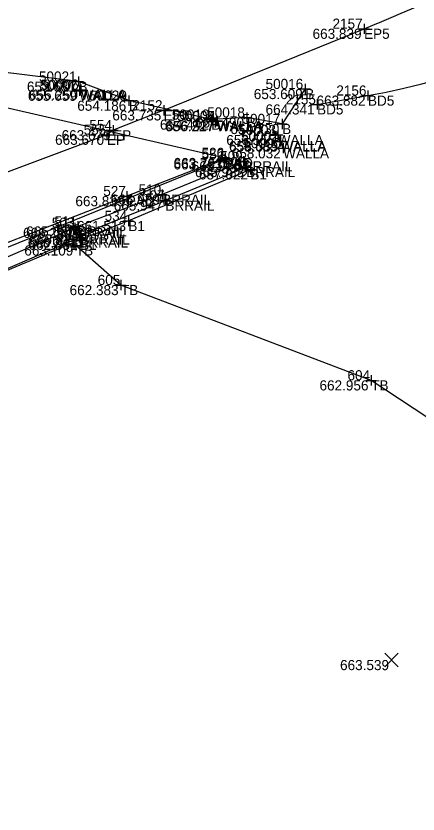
# Model space of a CAD drawing. Extents: x 2197382 to 2204062, y 634117 to 636522.
# Drawn here: x 2202423.3 to 2202463, y 635145.7 to 635224.5 of the extents above; entities that cross this region are included whole.
import ezdxf

# ---------------------------------------------------------------- set-up
doc = ezdxf.new("R2010")
doc.units = 0
for name, color, linetype in [('_CIVIL_CONSTRUCTION', 7, 'Continuous'), ('BR_P_Gen_Approach_Slab', 7, 'Continuous'), ('BR_X_SV_Abut_Text', 7, 'Continuous'), ('BR_X_SV_Deck_Top', 7, 'Continuous'), ('BR_X_SV_Deck_Top_Text', 7, 'Continuous'), ('BR_X_SV_Rail', 7, 'Continuous'), ('GE_P_Alignment_100_Distances', 7, 'Continuous'), ('GE_X_Alignment', 7, 'Continuous'), ('PF_P_Grade_Line', 7, 'Continuous'), ('RW_X_CL_100_Curve_Data', 7, 'Continuous'), ('RW_X_CL_100_Stations', 7, 'Continuous'), ('SH_Border', 7, 'Continuous'), ('SH_Cut_Line', 7, 'Continuous'), ('SH_Data', 7, 'Continuous'), ('SH_Text', 7, 'Continuous')]:
    doc.layers.add(name, color=color, linetype=linetype)

msp = doc.modelspace()

# ---------------------------------------------------------------- linework, layer by layer
at = {"layer": '_CIVIL_CONSTRUCTION'}
for p, q in [((2202457.668, 635223.782), (2202457.668, 635222.782)), ((2202457.168, 635223.282), (2202458.168, 635223.282)), ((2202457.668, 635223.282), (2202457.668, 635223.282)), ((2202429.476, 635218.562), (2202429.476, 635217.562)), ((2202428.976, 635218.062), (2202429.976, 635218.062)), ((2202429.476, 635218.062), (2202429.476, 635218.062)), ((2202429.568, 635217.662), (2202429.568, 635216.662)), ((2202429.705, 635217.763), (2202429.705, 635216.763)), ((2202451.866, 635217.83), (2202451.866, 635216.83)), ((2202429.068, 635217.162), (2202430.068, 635217.162)), ((2202429.205, 635217.263), (2202430.205, 635217.263)), ((2202429.568, 635217.162), (2202429.568, 635217.162)), ((2202429.705, 635217.263), (2202429.705, 635217.263)), ((2202434.466, 635216.679), (2202434.466, 635215.679)), ((2202451.366, 635217.33), (2202452.366, 635217.33)), ((2202451.866, 635217.33), (2202451.866, 635217.33)), ((2202457.551, 635216.681), (2202458.551, 635216.681)), ((2202458.051, 635217.181), (2202458.051, 635216.181)), ((2202458.051, 635216.681), (2202458.051, 635216.681)), ((2202433.966, 635216.179), (2202434.966, 635216.179)), ((2202434.466, 635216.179), (2202434.466, 635216.179)), ((2202453.028, 635216.312), (2202453.028, 635215.312)), ((2202437.39, 635215.225), (2202438.39, 635215.225)), ((2202437.89, 635215.725), (2202437.89, 635214.725)), ((2202437.89, 635215.225), (2202437.89, 635215.225)), ((2202452.528, 635215.812), (2202453.528, 635215.812)), ((2202453.028, 635215.812), (2202453.028, 635215.812)), ((2202442.093, 635214.307), (2202443.093, 635214.307)), ((2202442.593, 635214.807), (2202442.593, 635213.807)), ((2202442.593, 635214.307), (2202442.593, 635214.307)), ((2202443.118, 635214.648), (2202443.118, 635213.648)), ((2202443.18, 635214.673), (2202443.18, 635213.673)), ((2202445.6, 635214.518), (2202446.6, 635214.518)), ((2202446.1, 635215.018), (2202446.1, 635214.018)), ((2202446.1, 635214.518), (2202446.1, 635214.518)), ((2202449.583, 635214.376), (2202449.583, 635213.376)), ((2202432.899, 635213.763), (2202432.899, 635212.763)), ((2202442.618, 635214.148), (2202443.618, 635214.148)), ((2202442.68, 635214.173), (2202443.68, 635214.173)), ((2202443.118, 635214.148), (2202443.118, 635214.148)), ((2202443.18, 635214.173), (2202443.18, 635214.173)), ((2202449.083, 635213.876), (2202450.083, 635213.876)), ((2202449.583, 635213.876), (2202449.583, 635213.876)), ((2202431.787, 635212.815), (2202432.787, 635212.815)), ((2202432.287, 635213.315), (2202432.287, 635212.315)), ((2202432.287, 635212.815), (2202432.287, 635212.815)), ((2202432.399, 635213.263), (2202433.399, 635213.263)), ((2202432.899, 635213.263), (2202432.899, 635213.263)), ((2202448.641, 635212.788), (2202449.641, 635212.788)), ((2202449.141, 635213.288), (2202449.141, 635212.288)), ((2202449.141, 635212.788), (2202449.141, 635212.788)), ((2202448.901, 635212.192), (2202449.901, 635212.192)), ((2202448.93, 635212.14), (2202449.93, 635212.14)), ((2202449.401, 635212.692), (2202449.401, 635211.692)), ((2202449.401, 635212.192), (2202449.401, 635212.192)), ((2202449.43, 635212.64), (2202449.43, 635211.64)), ((2202449.43, 635212.14), (2202449.43, 635212.14)), ((2202449.678, 635211.981), (2202449.678, 635210.981)), ((2202449.178, 635211.481), (2202450.178, 635211.481)), ((2202449.678, 635211.481), (2202449.678, 635211.481)), ((2202443.426, 635210.385), (2202444.426, 635210.385)), ((2202443.45, 635210.52), (2202444.45, 635210.52)), ((2202443.926, 635210.885), (2202443.926, 635209.885)), ((2202443.926, 635210.385), (2202443.926, 635210.385)), ((2202443.95, 635211.02), (2202443.95, 635210.02)), ((2202443.95, 635210.52), (2202443.95, 635210.52)), ((2202445.763, 635210.697), (2202445.763, 635209.697)), ((2202445.263, 635210.197), (2202446.263, 635210.197)), ((2202445.545, 635209.625), (2202446.545, 635209.625)), ((2202445.763, 635210.197), (2202445.763, 635210.197)), ((2202446.045, 635210.125), (2202446.045, 635209.125)), ((2202446.045, 635209.625), (2202446.045, 635209.625)), ((2202446.445, 635209.895), (2202446.445, 635208.895)), ((2202445.945, 635209.395), (2202446.945, 635209.395)), ((2202446.445, 635209.395), (2202446.445, 635209.395)), ((2202434.242, 635207.252), (2202434.242, 635206.252)), ((2202437.75, 635207.408), (2202437.75, 635206.408)), ((2202433.742, 635206.752), (2202434.742, 635206.752)), ((2202434.242, 635206.752), (2202434.242, 635206.752)), ((2202437.25, 635206.908), (2202438.25, 635206.908)), ((2202437.75, 635206.908), (2202437.75, 635206.908)), ((2202438.058, 635206.817), (2202438.058, 635205.817)), ((2202437.558, 635206.317), (2202438.558, 635206.317)), ((2202438.058, 635206.317), (2202438.058, 635206.317)), ((2202429.129, 635204.122), (2202429.129, 635203.122)), ((2202429.41, 635204.264), (2202429.41, 635203.264)), ((2202433.902, 635204.297), (2202434.902, 635204.297)), ((2202434.402, 635204.797), (2202434.402, 635203.797)), ((2202434.402, 635204.297), (2202434.402, 635204.297)), ((2202428.629, 635203.622), (2202429.629, 635203.622)), ((2202428.91, 635203.764), (2202429.91, 635203.764)), ((2202429.129, 635203.622), (2202429.129, 635203.622)), ((2202429.41, 635203.764), (2202429.41, 635203.764)), ((2202429.701, 635203.466), (2202429.701, 635202.466)), ((2202429.059, 635202.673), (2202430.059, 635202.673)), ((2202429.201, 635202.966), (2202430.201, 635202.966)), ((2202429.559, 635203.173), (2202429.559, 635202.173)), ((2202429.559, 635202.673), (2202429.559, 635202.673)), ((2202429.637, 635202.941), (2202429.637, 635201.941)), ((2202429.701, 635202.966), (2202429.701, 635202.966)), ((2202428.719, 635201.88), (2202429.719, 635201.88)), ((2202429.137, 635202.441), (2202430.137, 635202.441)), ((2202429.219, 635202.38), (2202429.219, 635201.38)), ((2202429.219, 635201.88), (2202429.219, 635201.88)), ((2202429.637, 635202.441), (2202429.637, 635202.441)), ((2202433.169, 635197.969), (2202434.169, 635197.969)), ((2202433.669, 635198.469), (2202433.669, 635197.469)), ((2202433.669, 635197.969), (2202433.669, 635197.969)), ((2202457.873, 635188.556), (2202458.873, 635188.556)), ((2202458.373, 635189.056), (2202458.373, 635188.056)), ((2202458.373, 635188.556), (2202458.373, 635188.556))]:
    msp.add_line(p, q, dxfattribs=at)
at = {"layer": 'BR_P_Gen_Approach_Slab'}
msp.add_lwpolyline([(2202443.95, 635210.52), (2202434.242, 635206.752), (2202412.599, 635198.33), (2202410.833, 635202.436), (2202382.459, 635210.634), (2202380.356, 635214.567), (2202398.438, 635220.987)], close=True, dxfattribs=at)
at = {"layer": 'BR_X_SV_Deck_Top'}
msp.add_line((2202453.028, 635215.812), (2202458.051, 635216.681), dxfattribs=at)
msp.add_open_spline([(2202458.051, 635216.681), (2202477.116, 635219.979), (2202511.723, 635243.78), (2202554.955, 635262.299), (2202588.014, 635280.674), (2202608.342, 635292.387), (2202640.833, 635312.137), (2202668.147, 635329.948), (2202698.573, 635351.315), (2202722.135, 635368.649), (2202754.604, 635393.426), (2202777.494, 635412.293), (2202789.607, 635422.635)], degree=3, dxfattribs=at)
at = {"layer": 'BR_X_SV_Rail'}
for points in [[(2202429.701, 635202.966), (2202438.058, 635206.317), (2202446.045, 635209.625), (2202445.763, 635210.197), (2202437.75, 635206.908), (2202429.41, 635203.764)], [(2202416.881, 635197.212), (2202429.559, 635202.673), (2202429.129, 635203.622), (2202417.763, 635198.717), (2202416.562, 635197.807)]]:
    msp.add_lwpolyline(points, close=True, dxfattribs=at)
at = {"layer": 'GE_P_Alignment_100_Distances'}
for p, q in [((2202437.89, 635215.225), (2202457.668, 635223.282)), ((2202437.89, 635215.225), (2202432.899, 635213.263)), ((2202432.287, 635212.815), (2202386.45, 635195.588)), ((2202432.899, 635213.263), (2202432.287, 635212.815))]:
    msp.add_line(p, q, dxfattribs=at)
msp.add_open_spline([(2202457.668, 635223.282), (2202466.48, 635226.872), (2202500.455, 635242.355), (2202539.476, 635261.183), (2202573.06, 635279.52), (2202585.609, 635286.631), (2202599.84, 635294.842), (2202617.618, 635305.231), (2202642.294, 635320.395), (2202667.372, 635336.77), (2202691.723, 635353.633), (2202713.413, 635369.403), (2202739.641, 635388.973), (2202758.657, 635404.276), (2202770.061, 635413.813)], degree=3, dxfattribs=at)
at = {"layer": 'GE_X_Alignment'}
msp.add_line((2202443.926, 635210.385), (2202389.25, 635188.207), dxfattribs=at)
msp.add_open_spline([(2202540.057, 635152.933), (2202529.432, 635144.249), (2202507.229, 635123.458), (2202471.724, 635092.047), (2202435.624, 635056.757), (2202402.1, 635018.874), (2202368.735, 634981.476), (2202336.154, 634943.25), (2202304.623, 634904.212), (2202274.11, 634864.33), (2202244.375, 634823.829), (2202215.651, 634782.828), (2202187.652, 634741.046), (2202161.539, 634698.558), (2202134.843, 634655.997), (2202111.414, 634611.664), (2202087.713, 634567.523), (2202064.966, 634523.345), (2202044.201, 634477.974), (2202023.416, 634432.248), (2202003.663, 634386.184), (2201990.907, 634355.55), (2201984.79, 634340.333)], degree=3, dxfattribs=at)
at = {"layer": 'PF_P_Grade_Line'}
msp.add_lwpolyline([(2202485.179, 635170.855), (2202458.373, 635188.556), (2202433.669, 635197.969), (2202429.219, 635201.88)], dxfattribs=at)
at = {"layer": 'RW_X_CL_100_Curve_Data'}
for p, q in [((2202459.714, 635160.265), (2202461.048, 635161.6)), ((2202459.714, 635161.6), (2202461.048, 635160.265))]:
    msp.add_line(p, q, dxfattribs=at)
at = {"layer": 'SH_Text'}
for points in [[(2202451.866, 635217.33), (2202449.583, 635213.876), (2202446.1, 635214.518), (2202442.593, 635214.307), (2202434.466, 635216.179), (2202429.476, 635218.062), (2202421.727, 635219.033), (2202415.037, 635223.445)], [(2202446.445, 635209.395), (2202434.402, 635204.297), (2202429.637, 635202.441), (2202416.9, 635197.106), (2202416.266, 635197.969)]]:
    msp.add_lwpolyline(points, dxfattribs=at)

# ---------------------------------------------------------------- texts
at = {"layer": 'BR_X_SV_Abut_Text'}
for s, p in [('50006', (2202425.784, 635217.263)), ('50007', (2202425.655, 635217.162)), ('655.659', (2202424.484, 635216.162)), ('656.250', (2202424.591, 635216.263)), ('WALLA', (2202429.568, 635216.162)), ('WALLA', (2202429.705, 635216.263)), ('50005', (2202439.231, 635214.148)), ('50004', (2202439.241, 635214.173)), ('656.227', (2202438.022, 635213.148)), ('656.517', (2202438.084, 635213.173)), ('WALLA', (2202443.118, 635213.148)), ('WALLA', (2202443.18, 635213.173)), ('50003', (2202445.26, 635212.788)), ('656.555', (2202444.071, 635211.788)), ('50002', (2202445.511, 635212.192)), ('50001', (2202445.531, 635212.14)), ('WALLA', (2202449.141, 635211.788)), ('656.585', (2202444.331, 635211.192)), ('658.039', (2202444.346, 635211.14)), ('50000', (2202445.747, 635211.481)), ('WALLA', (2202449.401, 635211.192)), ('WALLA', (2202449.43, 635211.14)), ('658.032', (2202444.605, 635210.481)), ('WALLA', (2202449.678, 635210.481))]:
    msp.add_text(s, height=1, dxfattribs=at).set_placement(p)
at = {"layer": 'BR_X_SV_Deck_Top_Text'}
for s, p in [('2156', (2202454.928, 635216.681)), ('2155', (2202449.939, 635215.812)), ('663.882', (2202452.978, 635215.681)), ('BD5', (2202458.051, 635215.681)), ('664.341', (2202447.946, 635214.812)), ('BD5', (2202453.028, 635214.812))]:
    msp.add_text(s, height=1, dxfattribs=at).set_placement(p)
at = {"layer": 'RW_X_CL_100_Stations'}
for s, p in [('509', (2202443.459, 635210.197)), ('508', (2202443.724, 635209.625)), ('665.976', (2202440.659, 635209.197)), ('665.983', (2202440.981, 635208.625)), ('BRRAIL', (2202445.763, 635209.197)), ('BRRAIL', (2202446.045, 635208.625)), ('510', (2202435.416, 635206.908)), ('507', (2202435.742, 635206.317)), ('665.939', (2202432.666, 635205.908)), ('BRRAIL', (2202437.75, 635205.908)), ('665.947', (2202432.962, 635205.317)), ('BRRAIL', (2202438.058, 635205.317)), ('503', (2202426.844, 635203.622)), ('511', (2202427.108, 635203.764)), ('666.244', (2202424.007, 635202.622)), ('665.627', (2202424.314, 635202.764)), ('502', (2202427.265, 635202.673)), ('506', (2202427.376, 635202.966)), ('BRRAIL', (2202429.129, 635202.622)), ('BRRAIL', (2202429.41, 635202.764)), ('666.241', (2202424.477, 635201.673)), ('665.622', (2202424.628, 635201.966)), ('BRRAIL', (2202429.559, 635201.673)), ('BRRAIL', (2202429.701, 635201.966))]:
    msp.add_text(s, height=1, dxfattribs=at).set_placement(p)
at = {"layer": 'SH_Border'}
for s, p in [('EP5', (2202457.668, 635222.282)), ('B', (2202429.476, 635217.062)), ('B', (2202451.866, 635216.33)), ('B', (2202434.466, 635215.179)), ('EP5', (2202437.89, 635214.225)), ('B', (2202442.593, 635213.307)), ('B', (2202446.1, 635213.518)), ('B', (2202449.583, 635212.876)), ('EP', (2202432.287, 635211.815)), ('EP', (2202432.899, 635212.263)), ('EB', (2202443.926, 635209.385)), ('PAD', (2202443.95, 635209.52)), ('B1', (2202446.445, 635208.395)), ('PAD', (2202434.242, 635205.752)), ('B1', (2202434.402, 635203.297)), ('TB', (2202429.219, 635200.88)), ('B1', (2202429.637, 635201.441)), ('TB', (2202433.669, 635196.969)), ('TB', (2202458.373, 635187.556))]:
    msp.add_text(s, height=1, dxfattribs=at).set_placement(p)
at = {"layer": 'SH_Cut_Line'}
for s, p in [('2157', (2202454.553, 635223.282)), ('50021', (2202425.577, 635218.062)), ('50016', (2202447.945, 635217.33)), ('50020', (2202430.535, 635216.179)), ('2152', (2202434.798, 635215.225)), ('50019', (2202438.693, 635214.307)), ('50018', (2202442.183, 635214.518)), ('50017', (2202445.67, 635213.876)), ('555', (2202429.996, 635212.815)), ('554', (2202430.556, 635213.263)), ('526', (2202441.625, 635210.52)), ('552', (2202441.632, 635210.385)), ('533', (2202444.16, 635209.395)), ('527', (2202431.926, 635206.752)), ('534', (2202432.059, 635204.297)), ('535', (2202427.346, 635202.441)), ('606', (2202426.894, 635201.88)), ('605', (2202431.378, 635197.969)), ('604', (2202456.03, 635188.556))]:
    msp.add_text(s, height=1, dxfattribs=at).set_placement(p)
at = {"layer": 'SH_Data'}
for s, p in [('663.839', (2202452.584, 635222.282)), ('653.631', (2202424.394, 635217.062)), ('653.609', (2202446.782, 635216.33)), ('654.186', (2202429.362, 635215.179)), ('663.735', (2202432.82, 635214.225)), ('654.442', (2202437.52, 635213.307)), ('654.490', (2202440.986, 635213.518)), ('654.730', (2202444.469, 635212.876)), ('663.670', (2202427.173, 635211.815)), ('663.679', (2202427.815, 635212.263)), ('663.723', (2202438.862, 635209.385)), ('663.761', (2202438.868, 635209.52)), ('657.022', (2202441.372, 635208.395)), ('663.833', (2202429.178, 635205.752)), ('661.513', (2202429.338, 635203.297)), ('663.109', (2202424.135, 635200.88)), ('662.851', (2202424.555, 635201.441)), ('662.383', (2202428.605, 635196.969)), ('662.956', (2202453.269, 635187.556)), ('663.539', (2202455.297, 635159.933))]:
    msp.add_text(s, height=1, dxfattribs=at).set_placement(p)

doc.saveas('drawing.dxf')
